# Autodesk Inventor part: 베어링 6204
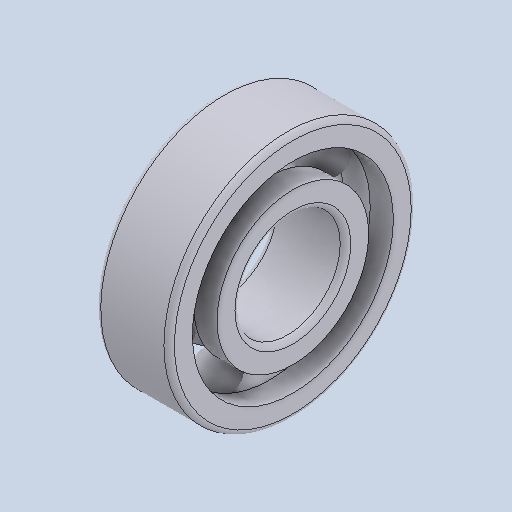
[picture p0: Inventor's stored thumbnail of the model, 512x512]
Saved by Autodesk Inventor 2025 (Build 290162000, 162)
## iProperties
Created: 2024-08
Part Number: 베어링 6204
Material: 강철, 연강
Description: 깊은 그루브 볼 베어링
Document SubType Name: Modeling
Designer: samsung
Density: 7.86 g/cm^3
Appearance: 기본값
Author: jhkim
Sending System: Autodesk Inventor 2025
Preprocessor: ST-DEVELOPER v20
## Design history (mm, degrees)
feature "Solid1"
feature "Solid1:1"
feature "Solid1:2"
feature "Solid1:3"
feature "Solid1:4"
feature "Solid1:5"
feature "Solid1:6"
feature "Solid1:7"
feature "Solid1:8"
node "솔리드1"
node "솔리드2"
node "솔리드3"
node "솔리드4"
node "솔리드5"
node "솔리드6"
node "솔리드7"
node "솔리드8"
node "솔리드9"
